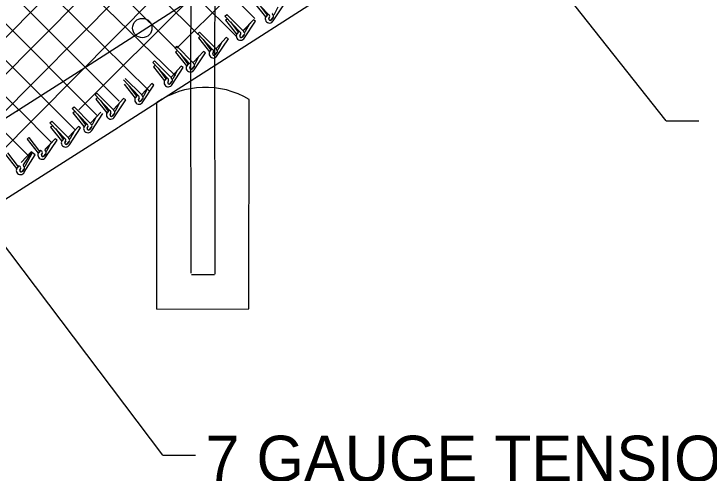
# Model space of a CAD drawing. Extents: x 0 to 2.85, y -0.1 to 1.83.
# Drawn here: x 1.7594 to 1.9115, y 1.3819 to 1.4824 of the extents above; entities that cross this region are included whole.
import ezdxf

# ---------------------------------------------------------------- set-up
doc = ezdxf.new("R2010")
doc.units = 0
for name, color, linetype in [('CT_Dimensions', 7, 'Continuous'), ('sb_Chainlink Fence', 7, 'Continuous'), ('sb_Earth', 7, 'Continuous'), ('sb_Existing Concrete', 7, 'Continuous'), ('sb_Existing Structural Steel', 7, 'Continuous')]:
    doc.layers.add(name, color=color, linetype=linetype)

msp = doc.modelspace()

# ---------------------------------------------------------------- linework, layer by layer
at = {"layer": 'CT_Dimensions'}
for p, q in [((1.9021660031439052, 1.4590312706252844), (1.8609873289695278, 1.5110686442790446)), ((1.9021660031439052, 1.4590312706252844), (1.9092764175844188, 1.4590312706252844)), ((1.7920044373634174, 1.3858294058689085), (1.74611189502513, 1.4465451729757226)), ((1.7920044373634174, 1.3858294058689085), (1.7991148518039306, 1.3858294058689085))]:
    msp.add_line(p, q, dxfattribs=at)
at = {"layer": 'sb_Chainlink Fence'}
for p, q in [((1.689092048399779, 1.4081735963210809), (1.9986754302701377, 1.720458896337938)), ((1.713665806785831, 1.4249653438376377), (1.998677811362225, 1.7124648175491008)), ((1.7334939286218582, 1.436970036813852), (1.9948211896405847, 1.700578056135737)), ((1.7532122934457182, 1.448864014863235), (1.998630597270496, 1.6964242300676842)), ((1.7736272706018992, 1.4614473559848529), (1.9971689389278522, 1.6849890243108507)), ((1.7950888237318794, 1.474947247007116), (1.9974037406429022, 1.6772621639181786)), ((1.7349460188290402, 1.558625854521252), (1.8121597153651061, 1.481412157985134)), ((1.7293783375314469, 1.5562318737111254), (1.8082147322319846, 1.4773954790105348)), ((1.727580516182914, 1.5500680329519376), (1.7997229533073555, 1.477925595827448)), ((1.7215126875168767, 1.548174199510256), (1.7947317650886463, 1.4749551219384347)), ((1.716204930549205, 1.5455202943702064), (1.7947645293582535, 1.4688543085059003)), ((1.7123356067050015, 1.5414279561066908), (1.7889703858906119, 1.4655716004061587)), ((1.705270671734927, 1.5405312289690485), (1.774946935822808, 1.4708549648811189)), ((1.7001417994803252, 1.5376984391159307), (1.7776412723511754, 1.4601989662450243)), ((1.6951924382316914, 1.5346861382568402), (1.7728832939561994, 1.4569952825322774)), ((1.6907662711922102, 1.5311506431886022), (1.7605489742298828, 1.4613679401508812)), ((1.685895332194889, 1.5280599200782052), (1.7624942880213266, 1.4514609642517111)), ((1.8151488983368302, 1.4823272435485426), (1.8119270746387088, 1.4857572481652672)), ((1.8120604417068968, 1.484831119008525), (1.8144700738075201, 1.4817938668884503)), ((1.813099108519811, 1.4844979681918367), (1.8147937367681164, 1.482186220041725)), ((1.8161694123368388, 1.4809619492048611), (1.8186097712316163, 1.4846482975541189)), ((1.8164483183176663, 1.4824171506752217), (1.8172615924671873, 1.4839678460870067)), ((1.8055949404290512, 1.4819829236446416), (1.8059911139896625, 1.4823411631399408)), ((1.808816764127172, 1.4785529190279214), (1.8055949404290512, 1.4819829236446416)), ((1.8096146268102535, 1.4786945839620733), (1.8059911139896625, 1.4823411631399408)), ((1.8145180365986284, 1.4818372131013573), (1.8144815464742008, 1.4817691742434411)), ((1.815007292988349, 1.4824139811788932), (1.8145155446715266, 1.4818351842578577)), ((1.8150138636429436, 1.4824229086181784), (1.8145180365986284, 1.4818372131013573)), ((1.8057283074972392, 1.481056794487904), (1.8061244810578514, 1.4814150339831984)), ((1.8057283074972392, 1.481056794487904), (1.8081379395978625, 1.4780195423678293)), ((1.8067669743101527, 1.4807236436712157), (1.8084616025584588, 1.4784118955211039)), ((1.8118319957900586, 1.4811791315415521), (1.8096597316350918, 1.4788440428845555)), ((1.8118319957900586, 1.4811791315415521), (1.8096735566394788, 1.478857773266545)), ((1.8098372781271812, 1.4771876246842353), (1.812277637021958, 1.4808739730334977)), ((1.812277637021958, 1.4808739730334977), (1.8118319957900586, 1.4811791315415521)), ((1.8144815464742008, 1.4817691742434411), (1.81445043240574, 1.4816963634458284)), ((1.8151961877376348, 1.4814335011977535), (1.8153601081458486, 1.4817876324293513)), ((1.815359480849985, 1.481775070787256), (1.8151965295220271, 1.4814415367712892)), ((1.8161225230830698, 1.4816307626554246), (1.8156768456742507, 1.481104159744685)), ((1.815717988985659, 1.4811474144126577), (1.8161225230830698, 1.4816307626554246)), ((1.8101161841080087, 1.478642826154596), (1.8109294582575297, 1.4801935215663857)), ((1.7996496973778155, 1.478102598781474), (1.800045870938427, 1.4784608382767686)), ((1.8028715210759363, 1.474672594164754), (1.7996496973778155, 1.478102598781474)), ((1.7997830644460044, 1.4771764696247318), (1.800179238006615, 1.4775347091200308)), ((1.8036693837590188, 1.4748142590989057), (1.800045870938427, 1.4784608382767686)), ((1.8058867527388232, 1.4772988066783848), (1.8037144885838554, 1.4749637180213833)), ((1.8058867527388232, 1.4772988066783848), (1.8037283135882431, 1.4749774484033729)), ((1.8063323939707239, 1.4769936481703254), (1.8058867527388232, 1.4772988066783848)), ((1.8081494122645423, 1.47799484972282), (1.8081182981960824, 1.4779220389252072)), ((1.80818590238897, 1.478062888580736), (1.8081494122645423, 1.47799484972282)), ((1.8086751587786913, 1.4786396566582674), (1.8081834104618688, 1.4780608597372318)), ((1.8086817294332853, 1.4786485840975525), (1.80818590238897, 1.478062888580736)), ((1.8088640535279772, 1.4776591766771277), (1.8090279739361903, 1.4780133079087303)), ((1.8090273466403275, 1.47800074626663), (1.8088643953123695, 1.4776672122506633)), ((1.8097903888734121, 1.4778564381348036), (1.8093447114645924, 1.4773298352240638)), ((1.8093858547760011, 1.4773730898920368), (1.8097903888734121, 1.4778564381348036)), ((1.7997830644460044, 1.4771764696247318), (1.8021926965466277, 1.474139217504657)), ((1.800821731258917, 1.476843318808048), (1.8025163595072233, 1.4745315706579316)), ((1.8038920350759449, 1.4733072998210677), (1.8063323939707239, 1.4769936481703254)), ((1.8041709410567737, 1.4747625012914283), (1.8049842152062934, 1.4763131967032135)), ((1.7946264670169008, 1.4750215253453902), (1.7950226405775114, 1.4753797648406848)), ((1.7978482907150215, 1.4715915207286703), (1.7946264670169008, 1.4750215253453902)), ((1.794759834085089, 1.474095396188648), (1.7951560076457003, 1.4744536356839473)), ((1.798646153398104, 1.471733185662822), (1.7950226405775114, 1.4753797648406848)), ((1.8008635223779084, 1.474217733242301), (1.7986912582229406, 1.4718826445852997)), ((1.8008635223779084, 1.474217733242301), (1.7987050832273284, 1.4718963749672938)), ((1.801309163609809, 1.473912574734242), (1.8008635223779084, 1.474217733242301)), ((1.802729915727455, 1.4747593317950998), (1.8022381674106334, 1.4741805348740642)), ((1.802736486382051, 1.4747682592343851), (1.8022406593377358, 1.4741825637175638)), ((1.794759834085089, 1.474095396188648), (1.797169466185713, 1.4710581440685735)), ((1.7957985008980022, 1.4737622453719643), (1.7974931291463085, 1.4714504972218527)), ((1.7988688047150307, 1.4702262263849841), (1.801309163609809, 1.473912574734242)), ((1.7991477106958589, 1.4716814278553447), (1.7999609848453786, 1.47323212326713)), ((1.8022041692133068, 1.4741145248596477), (1.802173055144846, 1.4740417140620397)), ((1.8022406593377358, 1.4741825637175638), (1.8022041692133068, 1.4741145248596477)), ((1.8029188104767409, 1.4737788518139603), (1.8030827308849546, 1.474132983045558)), ((1.8030821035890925, 1.4741204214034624), (1.8029191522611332, 1.4737868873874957)), ((1.8038451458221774, 1.4739761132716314), (1.8033994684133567, 1.4734495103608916)), ((1.8034406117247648, 1.4734927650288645), (1.8038451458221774, 1.4739761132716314)), ((1.7740540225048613, 1.4717105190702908), (1.782411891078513, 1.4633526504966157)), ((1.7897958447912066, 1.4717888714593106), (1.7901920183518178, 1.4721471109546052)), ((1.793017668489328, 1.4683588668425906), (1.7897958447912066, 1.4717888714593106)), ((1.7899292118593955, 1.4708627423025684), (1.7903253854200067, 1.4712209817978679)), ((1.7938155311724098, 1.4685005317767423), (1.7901920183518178, 1.4721471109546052)), ((1.7977066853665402, 1.471678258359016), (1.797214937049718, 1.4710994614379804)), ((1.7977132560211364, 1.4716871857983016), (1.797217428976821, 1.47110149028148)), ((1.7899292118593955, 1.4708627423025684), (1.7923388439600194, 1.4678254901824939)), ((1.790967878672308, 1.4705295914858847), (1.7926625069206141, 1.468217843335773)), ((1.7960329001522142, 1.4709850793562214), (1.793860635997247, 1.46864999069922)), ((1.7960329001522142, 1.4709850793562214), (1.7938744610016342, 1.4686637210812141)), ((1.7940381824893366, 1.4669935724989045), (1.796478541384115, 1.4706799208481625)), ((1.7943170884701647, 1.468448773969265), (1.795130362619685, 1.469999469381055)), ((1.796478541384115, 1.4706799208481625), (1.7960329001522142, 1.4709850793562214)), ((1.797180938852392, 1.4710334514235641), (1.7971498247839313, 1.470960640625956)), ((1.797217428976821, 1.47110149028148), (1.797180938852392, 1.4710334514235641)), ((1.797895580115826, 1.4706977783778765), (1.7980595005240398, 1.4710519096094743)), ((1.7980588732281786, 1.4710393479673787), (1.7978959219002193, 1.470705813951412)), ((1.7988219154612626, 1.4708950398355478), (1.798376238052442, 1.470368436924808)), ((1.7984173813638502, 1.4704116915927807), (1.7988219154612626, 1.4708950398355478)), ((1.7873913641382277, 1.4646903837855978), (1.7837678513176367, 1.4683369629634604)), ((1.792876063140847, 1.4684456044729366), (1.7923843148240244, 1.4678668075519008)), ((1.792882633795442, 1.468454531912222), (1.7923868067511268, 1.4678688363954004)), ((1.7865935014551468, 1.4645487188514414), (1.7833716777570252, 1.467978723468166)), ((1.7835050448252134, 1.4670525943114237), (1.7859146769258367, 1.464015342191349)), ((1.7845437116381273, 1.4667194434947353), (1.786238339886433, 1.4644076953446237)), ((1.7896087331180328, 1.4671749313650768), (1.7874364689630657, 1.4648398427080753)), ((1.7896087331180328, 1.4671749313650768), (1.7874502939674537, 1.4648535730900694)), ((1.7876140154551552, 1.463183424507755), (1.7900543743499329, 1.4668697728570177)), ((1.7900543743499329, 1.4668697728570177), (1.7896087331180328, 1.4671749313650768)), ((1.7923503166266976, 1.4678007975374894), (1.7923192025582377, 1.4677279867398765)), ((1.7923868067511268, 1.4678688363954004), (1.7923503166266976, 1.4678007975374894)), ((1.7930649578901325, 1.467465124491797), (1.7932288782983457, 1.4678192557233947)), ((1.7932282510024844, 1.467806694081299), (1.793065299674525, 1.4674731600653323)), ((1.7939912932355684, 1.4676623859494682), (1.7935456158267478, 1.467135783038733)), ((1.7935867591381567, 1.467179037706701), (1.7939912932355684, 1.4676623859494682)), ((1.7878929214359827, 1.4646386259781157), (1.7887061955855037, 1.4661893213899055)), ((1.7771850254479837, 1.4647243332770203), (1.7775811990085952, 1.465082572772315)), ((1.7804068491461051, 1.4612943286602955), (1.7771850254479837, 1.4647243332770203)), ((1.7773183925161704, 1.463798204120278), (1.777714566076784, 1.4641564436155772)), ((1.7773183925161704, 1.463798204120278), (1.7797280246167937, 1.4607609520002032)), ((1.7812047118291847, 1.461435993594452), (1.7775811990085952, 1.465082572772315)), ((1.7834220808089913, 1.463920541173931), (1.7812498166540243, 1.4615854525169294)), ((1.7834220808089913, 1.463920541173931), (1.781263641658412, 1.4615991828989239)), ((1.7814273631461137, 1.4599290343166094), (1.7838677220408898, 1.4636153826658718)), ((1.7838677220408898, 1.4636153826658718), (1.7834220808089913, 1.463920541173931)), ((1.7859261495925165, 1.4639906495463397), (1.7858950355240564, 1.463917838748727)), ((1.7859626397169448, 1.464058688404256), (1.7859261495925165, 1.4639906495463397)), ((1.7864518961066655, 1.4646354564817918), (1.785960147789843, 1.4640566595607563)), ((1.78645846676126, 1.4646443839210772), (1.7859626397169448, 1.464058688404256)), ((1.7866407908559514, 1.4636549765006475), (1.7868047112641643, 1.46400910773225)), ((1.7868040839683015, 1.4639965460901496), (1.7866411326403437, 1.4636630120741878)), ((1.7875671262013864, 1.4638522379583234), (1.7871214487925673, 1.4633256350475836)), ((1.7871625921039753, 1.4633688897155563), (1.7875671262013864, 1.4638522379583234)), ((1.7721778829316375, 1.4617438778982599), (1.772574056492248, 1.4621021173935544)), ((1.7761975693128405, 1.4584555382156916), (1.772574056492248, 1.4621021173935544)), ((1.7783570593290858, 1.4634650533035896), (1.7800516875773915, 1.461153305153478)), ((1.7817062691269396, 1.46138423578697), (1.7825195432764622, 1.4629349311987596)), ((1.7676168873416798, 1.4542955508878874), (1.760468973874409, 1.4614889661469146)), ((1.7753997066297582, 1.45831387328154), (1.7721778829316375, 1.4617438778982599)), ((1.7723112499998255, 1.4608177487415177), (1.7727074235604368, 1.4611759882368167)), ((1.7723112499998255, 1.4608177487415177), (1.7747208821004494, 1.4577804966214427)), ((1.7784149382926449, 1.4609400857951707), (1.7762426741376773, 1.458604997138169)), ((1.7784149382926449, 1.4609400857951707), (1.776256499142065, 1.4586187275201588)), ((1.7764202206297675, 1.4569485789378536), (1.7788605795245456, 1.4606349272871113)), ((1.7797394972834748, 1.4607362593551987), (1.779708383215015, 1.4606634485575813)), ((1.7797759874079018, 1.4608042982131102), (1.7797394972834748, 1.4607362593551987)), ((1.780265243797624, 1.4613810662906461), (1.7797734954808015, 1.4608022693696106)), ((1.7802718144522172, 1.4613899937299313), (1.7797759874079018, 1.4608042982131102)), ((1.7804541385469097, 1.4604005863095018), (1.7806180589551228, 1.4607547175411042)), ((1.7806174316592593, 1.4607421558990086), (1.7804544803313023, 1.4604086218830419)), ((1.7813804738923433, 1.4605978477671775), (1.7809347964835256, 1.4600712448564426)), ((1.7809759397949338, 1.4601144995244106), (1.7813804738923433, 1.4605978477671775)), ((1.773349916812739, 1.460484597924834), (1.775044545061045, 1.4581728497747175)), ((1.7766991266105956, 1.4584037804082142), (1.777512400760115, 1.4599544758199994)), ((1.7672997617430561, 1.4586065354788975), (1.7676959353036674, 1.458964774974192)), ((1.7705215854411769, 1.4551765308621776), (1.7672997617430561, 1.4586065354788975)), ((1.7674331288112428, 1.4576804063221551), (1.7678293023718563, 1.4580386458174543)), ((1.7674331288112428, 1.4576804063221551), (1.769842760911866, 1.4546431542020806)), ((1.7713194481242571, 1.4553181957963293), (1.7676959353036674, 1.458964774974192)), ((1.7735368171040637, 1.4578027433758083), (1.7713645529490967, 1.4554676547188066)), ((1.7735368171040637, 1.4578027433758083), (1.7713783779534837, 1.455481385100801)), ((1.7715420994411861, 1.4538112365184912), (1.7739824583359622, 1.457497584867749)), ((1.7739824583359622, 1.457497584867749), (1.7735368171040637, 1.4578027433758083)), ((1.7747323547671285, 1.4577558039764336), (1.7747012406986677, 1.4576829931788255)), ((1.7747688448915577, 1.4578238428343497), (1.7747323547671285, 1.4577558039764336)), ((1.7747920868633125, 1.4577099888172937), (1.7747609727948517, 1.457637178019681)), ((1.775258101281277, 1.4584006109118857), (1.7747663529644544, 1.45782181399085)), ((1.775264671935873, 1.458409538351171), (1.7747688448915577, 1.4578238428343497)), ((1.7748285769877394, 1.4577780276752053), (1.7747920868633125, 1.4577099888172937)), ((1.7754469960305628, 1.4574201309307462), (1.7756109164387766, 1.457774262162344)), ((1.775610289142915, 1.4577617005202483), (1.7754473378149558, 1.4574281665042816)), ((1.776373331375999, 1.4576173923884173), (1.7759276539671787, 1.4570907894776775)), ((1.7759687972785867, 1.4571340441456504), (1.776373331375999, 1.4576173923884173)), ((1.7684717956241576, 1.4573472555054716), (1.7701664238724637, 1.4550355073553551)), ((1.771821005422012, 1.4552664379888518), (1.7726342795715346, 1.456817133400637)), ((1.76230612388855, 1.4549912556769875), (1.7627022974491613, 1.4553494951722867)), ((1.76230612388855, 1.4549912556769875), (1.764715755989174, 1.4519540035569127)), ((1.7627022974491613, 1.4553494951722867), (1.7650394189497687, 1.4523463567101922)), ((1.7684098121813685, 1.4551135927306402), (1.7662375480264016, 1.452778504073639)), ((1.7684098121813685, 1.4551135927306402), (1.7662513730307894, 1.4527922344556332)), ((1.766415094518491, 1.4511220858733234), (1.7688554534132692, 1.4548084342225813)), ((1.7688554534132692, 1.4548084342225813), (1.7684098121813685, 1.4551135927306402)), ((1.7696650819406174, 1.4550208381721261), (1.7696339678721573, 1.4549480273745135)), ((1.7697015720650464, 1.4550888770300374), (1.7696650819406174, 1.4550208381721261)), ((1.7698542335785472, 1.4546184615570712), (1.7698231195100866, 1.4545456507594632)), ((1.7698907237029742, 1.4546865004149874), (1.7698542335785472, 1.4546184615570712)), ((1.7703799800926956, 1.4552632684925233), (1.769888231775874, 1.4546844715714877)), ((1.7703865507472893, 1.4552721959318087), (1.7698907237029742, 1.4546865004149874)), ((1.770568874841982, 1.4542827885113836), (1.7707327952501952, 1.4546369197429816)), ((1.7707321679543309, 1.4546243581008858), (1.7705692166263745, 1.454290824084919)), ((1.7714952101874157, 1.4544800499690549), (1.7710495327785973, 1.453953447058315)), ((1.7710906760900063, 1.4539967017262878), (1.7714952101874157, 1.4544800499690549)), ((1.76669400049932, 1.4525772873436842), (1.7675072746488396, 1.4541279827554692)), ((1.7575715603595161, 1.451634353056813), (1.75998119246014, 1.4485971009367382)), ((1.757967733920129, 1.4519925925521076), (1.7603048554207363, 1.4489894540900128)), ((1.763197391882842, 1.4522746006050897), (1.761025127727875, 1.4499395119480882)), ((1.763197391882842, 1.4522746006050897), (1.761038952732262, 1.4499532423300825)), ((1.7615145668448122, 1.4494327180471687), (1.7633168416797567, 1.4521551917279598)), ((1.7616805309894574, 1.447765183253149), (1.7640742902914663, 1.4516168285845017)), ((1.7619594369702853, 1.449220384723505), (1.7634528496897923, 1.45206792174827)), ((1.7640742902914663, 1.4516168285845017), (1.763197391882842, 1.4522746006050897)), ((1.7647272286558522, 1.4519293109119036), (1.7646961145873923, 1.4518565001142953)), ((1.7647637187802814, 1.4519973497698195), (1.7647272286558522, 1.4519293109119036)), ((1.7652529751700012, 1.4525741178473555), (1.7647612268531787, 1.4519953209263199)), ((1.7652595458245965, 1.4525830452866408), (1.7647637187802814, 1.4519973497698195)), ((1.765441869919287, 1.4515936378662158), (1.7656057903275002, 1.4519477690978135)), ((1.7656051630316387, 1.4519352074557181), (1.7654422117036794, 1.4516016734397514)), ((1.7663682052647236, 1.451790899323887), (1.765922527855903, 1.4512642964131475)), ((1.765963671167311, 1.4513075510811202), (1.7663682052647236, 1.451790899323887)), ((1.7599926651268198, 1.448572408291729), (1.7599615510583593, 1.4484995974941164)), ((1.7600291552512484, 1.4486404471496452), (1.7599926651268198, 1.448572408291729)), ((1.7605184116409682, 1.4492172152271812), (1.7600266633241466, 1.4486384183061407)), ((1.7605249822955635, 1.4492261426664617), (1.7600291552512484, 1.4486404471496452)), ((1.7607073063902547, 1.4482367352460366), (1.7608712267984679, 1.448590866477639)), ((1.760870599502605, 1.4485783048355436), (1.760707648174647, 1.448244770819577)), ((1.7616336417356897, 1.4484339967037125), (1.7611879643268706, 1.447907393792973)), ((1.761229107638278, 1.4479506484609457), (1.7616336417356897, 1.4484339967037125))]:
    msp.add_line(p, q, dxfattribs=at)
for centre, radius, start, end in [((1.8153314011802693, 1.4813775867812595), 0.0009354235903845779, 150.71281129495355, 333.6194641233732), ((1.8149725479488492, 1.4819473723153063), 0.0004188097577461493, 336.42296563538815, 65.09751420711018), ((1.8161963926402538, 1.4824615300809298), 0.0002558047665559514, 138.96114269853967, 350.00923971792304), ((1.8158528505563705, 1.4819138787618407), 0.00039099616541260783, 313.60686611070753, 52.174038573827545), ((1.8158633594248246, 1.4819143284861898), 0.00038439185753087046, 320.1413408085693, 52.94493342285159), ((1.815484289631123, 1.4813406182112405), 0.0003049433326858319, 160.6740382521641, 309.1570792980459), ((1.8154853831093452, 1.4813420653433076), 0.0003033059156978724, 162.454436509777, 320.07648952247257), ((1.8098642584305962, 1.4786872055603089), 0.0002558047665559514, 138.96114269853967, 350.00923971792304), ((1.8089992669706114, 1.4776032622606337), 0.0009354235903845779, 150.71281129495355, 333.6194641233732), ((1.8086404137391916, 1.478173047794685), 0.0004188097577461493, 336.42296563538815, 65.09751420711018), ((1.8091521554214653, 1.4775662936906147), 0.0003049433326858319, 160.6740382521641, 309.1570792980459), ((1.8091532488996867, 1.4775677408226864), 0.0003033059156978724, 162.454436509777, 320.07648952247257), ((1.8095207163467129, 1.4781395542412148), 0.00039099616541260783, 313.60686611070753, 52.174038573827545), ((1.809531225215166, 1.4781400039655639), 0.00038439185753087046, 320.1413408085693, 52.94493342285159), ((1.8026951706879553, 1.4742927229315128), 0.0004188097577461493, 336.42296563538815, 65.09751420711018), ((1.8039190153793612, 1.4748068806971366), 0.0002558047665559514, 138.96114269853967, 350.00923971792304), ((1.803575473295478, 1.4742592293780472), 0.00039099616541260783, 313.60686611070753, 52.174038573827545), ((1.8035859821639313, 1.4742596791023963), 0.00038439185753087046, 320.1413408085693, 52.94493342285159), ((1.803054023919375, 1.4737229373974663), 0.0009354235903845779, 150.71281129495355, 333.6194641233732), ((1.803206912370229, 1.4736859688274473), 0.0003049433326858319, 160.6740382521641, 309.1570792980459), ((1.8032080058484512, 1.4736874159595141), 0.0003033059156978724, 162.454436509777, 320.07648952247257), ((1.7976719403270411, 1.471211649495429), 0.0004188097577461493, 336.42296563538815, 65.09751420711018), ((1.7988957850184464, 1.4717258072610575), 0.0002558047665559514, 138.96114269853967, 350.00923971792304), ((1.7985522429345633, 1.4711781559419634), 0.00039099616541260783, 313.60686611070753, 52.174038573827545), ((1.7985627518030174, 1.4711786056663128), 0.00038439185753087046, 320.1413408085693, 52.94493342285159), ((1.7980307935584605, 1.4706418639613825), 0.0009354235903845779, 150.71281129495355, 333.6194641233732), ((1.7981836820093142, 1.4706048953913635), 0.0003049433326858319, 160.6740382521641, 309.1570792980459), ((1.7981847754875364, 1.4706063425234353), 0.0003033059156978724, 162.454436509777, 320.07648952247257), ((1.792841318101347, 1.4679789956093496), 0.0004188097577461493, 336.42296563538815, 65.09751420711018), ((1.7940651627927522, 1.4684931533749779), 0.0002558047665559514, 138.96114269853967, 350.00923971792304), ((1.7937216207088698, 1.4679455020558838), 0.00039099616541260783, 313.60686611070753, 52.174038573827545), ((1.793732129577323, 1.4679459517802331), 0.00038439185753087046, 320.1413408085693, 52.94493342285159), ((1.793200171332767, 1.467409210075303), 0.0009354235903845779, 150.71281129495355, 333.6194641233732), ((1.7933530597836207, 1.467372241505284), 0.0003049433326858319, 160.6740382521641, 309.1570792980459), ((1.7933541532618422, 1.4673736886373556), 0.0003033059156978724, 162.454436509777, 320.07648952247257), ((1.7867760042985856, 1.4635990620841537), 0.0009354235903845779, 150.71281129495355, 333.6194641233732), ((1.7864171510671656, 1.4641688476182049), 0.0004188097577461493, 336.42296563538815, 65.09751420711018), ((1.7869288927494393, 1.4635620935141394), 0.0003049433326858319, 160.6740382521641, 309.1570792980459), ((1.7869299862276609, 1.4635635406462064), 0.0003033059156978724, 162.454436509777, 320.07648952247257), ((1.7876409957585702, 1.4646830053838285), 0.0002558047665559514, 138.96114269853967, 350.00923971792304), ((1.787297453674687, 1.4641353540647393), 0.00039099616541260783, 313.60686611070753, 52.174038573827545), ((1.7873079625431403, 1.4641358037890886), 0.00038439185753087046, 320.1413408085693, 52.94493342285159), ((1.7805893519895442, 1.4603446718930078), 0.0009354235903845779, 150.71281129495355, 333.6194641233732), ((1.7802304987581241, 1.4609144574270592), 0.0004188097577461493, 336.42296563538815, 65.09751420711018), ((1.7814543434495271, 1.461428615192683), 0.0002558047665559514, 138.96114269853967, 350.00923971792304), ((1.781110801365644, 1.4608809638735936), 0.00039099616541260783, 313.60686611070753, 52.174038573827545), ((1.7811213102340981, 1.4608814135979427), 0.00038439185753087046, 320.1413408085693, 52.94493342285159), ((1.7807422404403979, 1.4603077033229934), 0.0003049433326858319, 160.6740382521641, 309.1570792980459), ((1.7807433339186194, 1.4603091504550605), 0.0003033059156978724, 162.454436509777, 320.07648952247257), ((1.775582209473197, 1.4573642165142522), 0.0009354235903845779, 150.71281129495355, 333.6194641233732), ((1.775223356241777, 1.4579340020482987), 0.0004188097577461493, 336.42296563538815, 65.09751420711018), ((1.776447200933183, 1.4584481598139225), 0.0002558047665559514, 138.96114269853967, 350.00923971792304), ((1.7761036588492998, 1.457900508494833), 0.00039099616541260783, 313.60686611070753, 52.174038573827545), ((1.7761141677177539, 1.4579009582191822), 0.00038439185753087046, 320.1413408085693, 52.94493342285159), ((1.7757350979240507, 1.4573272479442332), 0.0003049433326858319, 160.6740382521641, 309.1570792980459), ((1.775736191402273, 1.4573286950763), 0.0003033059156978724, 162.454436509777, 320.07648952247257), ((1.7707040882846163, 1.4542268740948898), 0.0009354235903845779, 150.71281129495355, 333.6194641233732), ((1.7703452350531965, 1.4547966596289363), 0.0004188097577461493, 336.42296563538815, 65.09751420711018), ((1.7715690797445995, 1.4553108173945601), 0.0002558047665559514, 138.96114269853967, 350.00923971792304), ((1.7712255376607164, 1.4547631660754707), 0.00039099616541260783, 313.60686611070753, 52.174038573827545), ((1.7712360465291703, 1.4547636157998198), 0.00038439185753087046, 320.1413408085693, 52.94493342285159), ((1.7708569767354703, 1.4541899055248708), 0.0003049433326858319, 160.6740382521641, 309.1570792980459), ((1.7708580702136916, 1.4541913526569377), 0.0003033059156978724, 162.454436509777, 320.07648952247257), ((1.7655770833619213, 1.451537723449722), 0.0009354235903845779, 150.71281129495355, 333.6194641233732), ((1.7652182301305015, 1.4521075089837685), 0.0004188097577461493, 336.42296563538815, 65.09751420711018), ((1.7657299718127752, 1.4515007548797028), 0.0003049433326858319, 160.6740382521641, 309.1570792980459), ((1.7657310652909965, 1.4515022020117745), 0.0003033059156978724, 162.454436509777, 320.07648952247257), ((1.7664420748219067, 1.452621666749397), 0.0002558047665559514, 138.96114269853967, 350.00923971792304), ((1.7660985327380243, 1.452074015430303), 0.00039099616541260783, 313.60686611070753, 52.174038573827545), ((1.7661090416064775, 1.452074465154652), 0.00038439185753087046, 320.1413408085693, 52.94493342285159), ((1.7608425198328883, 1.4481808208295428), 0.0009354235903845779, 150.71281129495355, 333.6194641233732), ((1.7604836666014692, 1.4487506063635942), 0.0004188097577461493, 336.42296563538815, 65.09751420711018), ((1.7617075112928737, 1.4492647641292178), 0.0002558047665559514, 138.96114269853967, 350.00923971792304), ((1.7613639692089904, 1.4487171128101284), 0.00039099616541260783, 313.60686611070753, 52.174038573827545), ((1.7613744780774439, 1.4487175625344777), 0.00038439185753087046, 320.1413408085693, 52.94493342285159), ((1.760995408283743, 1.4481438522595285), 0.0003049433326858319, 160.6740382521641, 309.1570792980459), ((1.7609965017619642, 1.4481452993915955), 0.0003033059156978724, 162.454436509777, 320.07648952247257)]:
    msp.add_arc(centre, radius, start, end, dxfattribs=at)
at = {"layer": 'sb_Earth'}
for p, q in [((1.7823436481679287, 1.4576862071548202), (1.997309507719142, 1.5957180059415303)), ((1.5044215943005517, 1.2815901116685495), (1.7823218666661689, 1.4576319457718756))]:
    msp.add_line(p, q, dxfattribs=at)
at = {"layer": 'sb_Existing Concrete'}
for p, q in [((1.8108470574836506, 1.417870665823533), (1.8108899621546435, 1.4637371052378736)), ((1.7906840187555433, 1.4178091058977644), (1.7906791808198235, 1.4630323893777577)), ((1.7906840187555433, 1.4178091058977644), (1.8108470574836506, 1.417870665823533))]:
    msp.add_line(p, q, dxfattribs=at)
msp.add_arc((1.8013339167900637, 1.4476298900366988), 0.01872859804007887, 59.32030537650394, 124.6736909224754, dxfattribs=at)
at = {"layer": 'sb_Existing Structural Steel'}
for p, q in [((1.7742550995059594, 1.4702761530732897), (1.9983734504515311, 1.614204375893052)), ((1.7981557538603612, 1.4720658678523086), (1.7982827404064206, 1.6073621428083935)), ((1.8034024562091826, 1.4755320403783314), (1.803566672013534, 1.6074162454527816)), ((1.8034293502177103, 1.4254468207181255), (1.8034024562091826, 1.4755320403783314)), ((1.798181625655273, 1.4256947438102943), (1.7981557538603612, 1.4720658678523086)), ((1.5021906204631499, 1.296704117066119), (1.7742550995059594, 1.4702761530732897)), ((1.7600728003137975, 1.4611307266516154), (1.760468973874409, 1.4614889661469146)), ((1.7983041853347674, 1.425416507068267), (1.8032818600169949, 1.425416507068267))]:
    msp.add_line(p, q, dxfattribs=at)
msp.add_circle((1.7875017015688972, 1.4793540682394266), 0.0021204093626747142, dxfattribs=at)

# ---------------------------------------------------------------- texts
at = {"layer": 'CT_Dimensions'}
msp.add_text('7 GAUGE TENSION WIRE AND', height=0.01, dxfattribs=at).set_placement((1.801334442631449, 1.3800917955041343))

doc.saveas('drawing.dxf')
